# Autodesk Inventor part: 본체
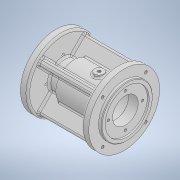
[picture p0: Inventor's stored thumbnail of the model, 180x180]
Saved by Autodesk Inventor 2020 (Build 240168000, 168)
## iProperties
Created: 2024-10
Part Number: 본체
Material: 일반
Document SubType Name: Modeling
Designer: oem
Density: 1 g/cm^3
Appearance: 기본값
Author: oem
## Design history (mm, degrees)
sketch "스케치1"
  geometry: L1 (-61, 0)-(61, 0); L2 (-61, 42)-(-56, 42); L3 (-56, 42)-(-56, 58); L4 (-56, 58)-(-44, 58); L5 (-44, 58)-(-44, 23); L6 (44, 58)-(56, 58); L7 (56, 58)-(56, 42); L8 (56, 42)-(61, 42); L9 (61, 42)-(61, 0); L10 (-61, 42)-(-61, 0); L11 (44, 58)-(44, 30); L12 (-44, 23)-(-29, 23); L13 (-29, 23)-(-29, 30); L14 (-29, 30)-(44, 30); 2 further points
  constraints: 28 end point, 7 perpendicular, 3 horizontal, 2 vertical, 1 coincident, 1 midpoint
  dimensions: "d0" = 122 distance of L1.start L1.end; "d1" = 5 distance of L2.start L2.end; "d3" = 116 diameter of L4 L1; "d4" = 84 diameter of L2 L1; "d5" = 116 diameter of L6 L1; "d6" = 84 diameter of L8 L1; "d7" = 5 distance of L7.end L8.end; "d8" = 12 distance of L6.start L6.end; "d9" = 15 distance of L5.end L12.end; "d10" = 46 diameter of L12 L1; "d11" = 60 diameter of L14 L1; "d12" = 12 distance of L3.end L4.end
revolve "회전1" sketch "스케치1" stored, may be unused: angle "d13" = 90 deg
sketch "스케치2"
  geometry: L1 (-41.012, 41.012)-(41.012, -41.012); L2 (41.012, 41.012)-(-41.012, -41.012); L3 (38.043, 38.043)-(21.213, 21.213); L4 (34.648, 41.719)-(12.339, 19.41); L5 (19.41, 12.339)-(41.719, 34.648); L6 (-38.043, 38.043)-(-21.213, 21.213); L7 (-41.719, 34.648)-(-19.41, 12.339); L8 (-12.339, 19.41)-(-34.648, 41.719); L9 (-41.719, 34.648)-(-34.648, 41.719); L10 (34.648, 41.719)-(41.719, 34.648); L11 (-58, 0)-(58, 0); C1 r 58 at (0, 0) reference; A1 r 30 centre (0, 0) between (21.213, 21.213) and (-21.213, 21.213) reference; A2 r 58 centre (0, 0) between (-41.012, 41.012) and (41.012, -41.012) reference; A3 r 23 centre (0, 0) between (12.339, 19.41) and (19.41, 12.339); 4 further points
  constraints: 26 end point, 12 point on circle, 4 point on line, 3 coincident, 3 midpoint, 2 parallel, 2 vertical alignment, 1 centre point, 1 horizontal
  dimensions: "d15" = 90 deg angle of L2 L1; "d18" = 54 distance from line of C1.centre L9; "d19" = 54 distance from line of L10 A1.centre; "d20" = 8.41512 horizontal distance of L6.end point (-29.628, 29.628); "d21" = 5 distance between parallel lines of L3 L4; "d22" = 5 distance between parallel lines of L8 L1; "d23" = 76.08689 distance of L3.start L6.start; "d24" = 10 distance of L7.start L8.end; "d25" = 10 distance of L4.start L5.end; "d28" = 46 diameter of A3; "d29" = 69.29646 distance of L4.start L8.end; "d30" = 83.4386 distance of L5.end L7.start
extrude "돌출1" join sketch "스케치2" stored distance "d26" = 10; taper "d27" = 0 deg
chamfer "모따기1" distance "d42" = 1; stored, may be unused: second distance "d43" = 2, angle "d44" = 45 deg
fillet "모깎기1" dims "d45" = 3
fillet "모깎기2" dims "d46" = 3
sketch "스케치5"
  geometry: C1 r 41 at (0, 0) reference; C2 r 36 at (0, 0)
  constraints: 1 centre point, 1 coincident
  dimensions: "d50" = 72 diameter of C2
extrude "돌출3" cut sketch "스케치5" distance "d51" = 3; taper "d52" = 0 deg
sketch "스케치6"
  geometry: C1 r 36 at (0, 0) reference; C2 r 21 at (0, 0)
  constraints: 1 centre point, 1 coincident
  dimensions: "d53" = 42 diameter of C2
extrude "돌출4" cut sketch "스케치6" distance "d54" = 16; taper "d55" = 0 deg
sketch "스케치7"
  geometry: C1 r 21 at (0, 0) reference; C2 r 25 at (0, 0)
  constraints: 1 centre point, 1 coincident
  dimensions: "d56" = 50 diameter of C2
extrude "돌출5" cut sketch "스케치7" distance "d57" = 54; taper "d58" = 0 deg
sketch "스케치9"
  geometry: C1 r 25 at (0, 0) reference; C2 r 21 at (0, 0)
  constraints: 1 centre point, 1 coincident
  dimensions: "d59" = 42 diameter of C2
extrude "돌출6" cut sketch "스케치9" distance "d60" = 12; taper "d61" = 0 deg
sketch "스케치10"
  geometry: C1 r 21 at (0, 0) reference; C2 r 18 at (0, 0)
  constraints: 1 centre point, 1 coincident
  dimensions: "d62" = 36 diameter of C2
extrude "돌출7" cut sketch "스케치10" distance "d63" = 18; taper "d64" = 0 deg
sketch "스케치11"
  geometry: C1 r 18 at (0, 0) reference; C2 r 16 at (0, 0)
  constraints: 1 centre point, 1 coincident
  dimensions: "d65" = 32 diameter of C2
extrude "돌출8" cut sketch "스케치11" distance "d66" = 4; taper "d67" = 0 deg
sketch "스케치12"
  geometry: C1 r 16 at (0, 0) reference; C2 r 10.5 at (0, 0)
  constraints: 1 centre point, 1 coincident
  dimensions: "d68" = 21 diameter of C2
extrude "돌출9" cut sketch "스케치12" distance "d69" = 3; taper "d70" = 0 deg
fillet "모깎기3" dims "d71" = 0.6
fillet "모깎기4" dims "d72" = 3
chamfer "모따기2" distance "d73" = 1; stored, may be unused: second distance "d74" = 2, angle "d75" = 45 deg
sketch "스케치13"
  geometry: C1 r 10.5 at (0, 0) reference; C2 r 36 at (0, 0)
  constraints: 1 centre point, 1 coincident
  dimensions: "d76" = 72 diameter of C2
extrude "돌출10" cut sketch "스케치13" distance "d77" = 4; taper "d78" = 0 deg
fillet "모깎기5" dims "d79" = 3
sketch "스케치14"
  geometry: C1 r 21 at (0, 0) reference; 1 further point
  constraints: 1 horizontal alignment
  dimensions: "d80" = 28 distance of point (28, 0) C1.centre
hole "구멍2" sketch "스케치14" at (28, 0) diameter "d81" = 4.134; stored, may be unused: countersink angle "d85" = 90 deg, drill point angle "d87" = 118 deg; dims "d82" = 12, "d83" = 11, "d84" = 6.6, "d86" = 14
sketch "스케치15"
  geometry: L1 (-35.355, 35.355)-(35.355, -35.355); L2 (35.355, 35.355)-(-35.355, -35.355); C1 r 42 at (0, 0) reference; A1 r 50 centre (0, 0) between (35.355, 35.355) and (35.355, -35.355)
  constraints: 4 end point, 4 point on circle, 2 horizontal alignment, 1 centre point, 1 coincident, 1 vertical alignment
  dimensions: "d91" = 100 diameter of A1; "d92" = 90 deg angle of L2 L1
hole "구멍3" sketch "스케치15" at (35.355, 35.355), (35.355, -35.355), (-35.355, 35.355), (-35.355, -35.355) diameter "d93" = 4.917; stored, may be unused: countersink angle "d97" = 90 deg, drill point angle "d99" = 118 deg; dims "d94" = 12, "d95" = 11, "d96" = 6.6, "d98" = 14
fillet "모깎기6" dims "d100" = 3
fillet "모깎기7" dims "d101" = 3
node "작업 평면2"
sketch "스케치16"
  geometry: L1 (-44, 0)-(-44, -55) reference; C1 r 7.5 at (-15, 0); 2 further points
  constraints: 1 centre point, 1 coincident, 1 horizontal alignment
  dimensions: "d104" = 29 distance from line of L1 point (-15, 0); "d105" = 15 diameter of C1
extrude "돌출11" join sketch "스케치16" stored distance "d106" = 4; taper "d107" = 0 deg
sketch "스케치17"
  geometry: C1 r 7.5 at (0, 0) reference; 1 further point
hole "구멍4" sketch "스케치17" at (0, 0) diameter "d108" = 5.1881; stored, may be unused: countersink angle "d112" = 90 deg, drill point angle "d114" = 118 deg; dims "d109" = 12, "d110" = 11, "d111" = 6.6, "d113" = 16
fillet "모깎기9" dims "d115" = 3
node "작업 평면4"
sketch "스케치19"
  geometry: L1 (61, 41)-(61, -41) reference; 2 further points
  constraints: 1 horizontal alignment, 1 other
  dimensions: "d118" = 52 distance from line of L1 point (9, 0)
feature "엠보싱1" sketch "스케치19" dims "d0" = 122, "d1" = 5, "d3" = 116, "d4" = 84, "d5" = 116, "d6" = 84, "d7" = 5, "d8" = 12, "d9" = 15, "d10" = 46, "d11" = 60, "d12" = 12, "d119" = 0.5, "d120" = 0
node "작업 평면5"
node "솔리드1"
mirror "미러1"
pattern_circular "원형 패턴2" dims angle "d89" = 360 deg
mirror "미러2"
mirror "미러3"
node "작업 평면1"
node "작업 평면3"
feature "A9D066F2-1C7D-4E18-AEED-F7BC21143FA4" dims "d81" = 4.134, "d82" = 12, "d83" = 11, "d84" = 6.6, "d85" = 90 deg, "d86" = 14, "d87" = 118 deg
other parameters: "d103" = -34
